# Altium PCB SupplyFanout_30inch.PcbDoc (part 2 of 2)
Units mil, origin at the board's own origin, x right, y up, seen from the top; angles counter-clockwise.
Board outline 6605 x 4500 mil, 4 copper layers (Top Layer, Int1 (GND), Int2 (PWR), Bottom Layer), stack 53.912 mil thick; 152 components, 62 nets, 512 pads, 47 vias.
Unrouted connection lines stored in the file: 85.
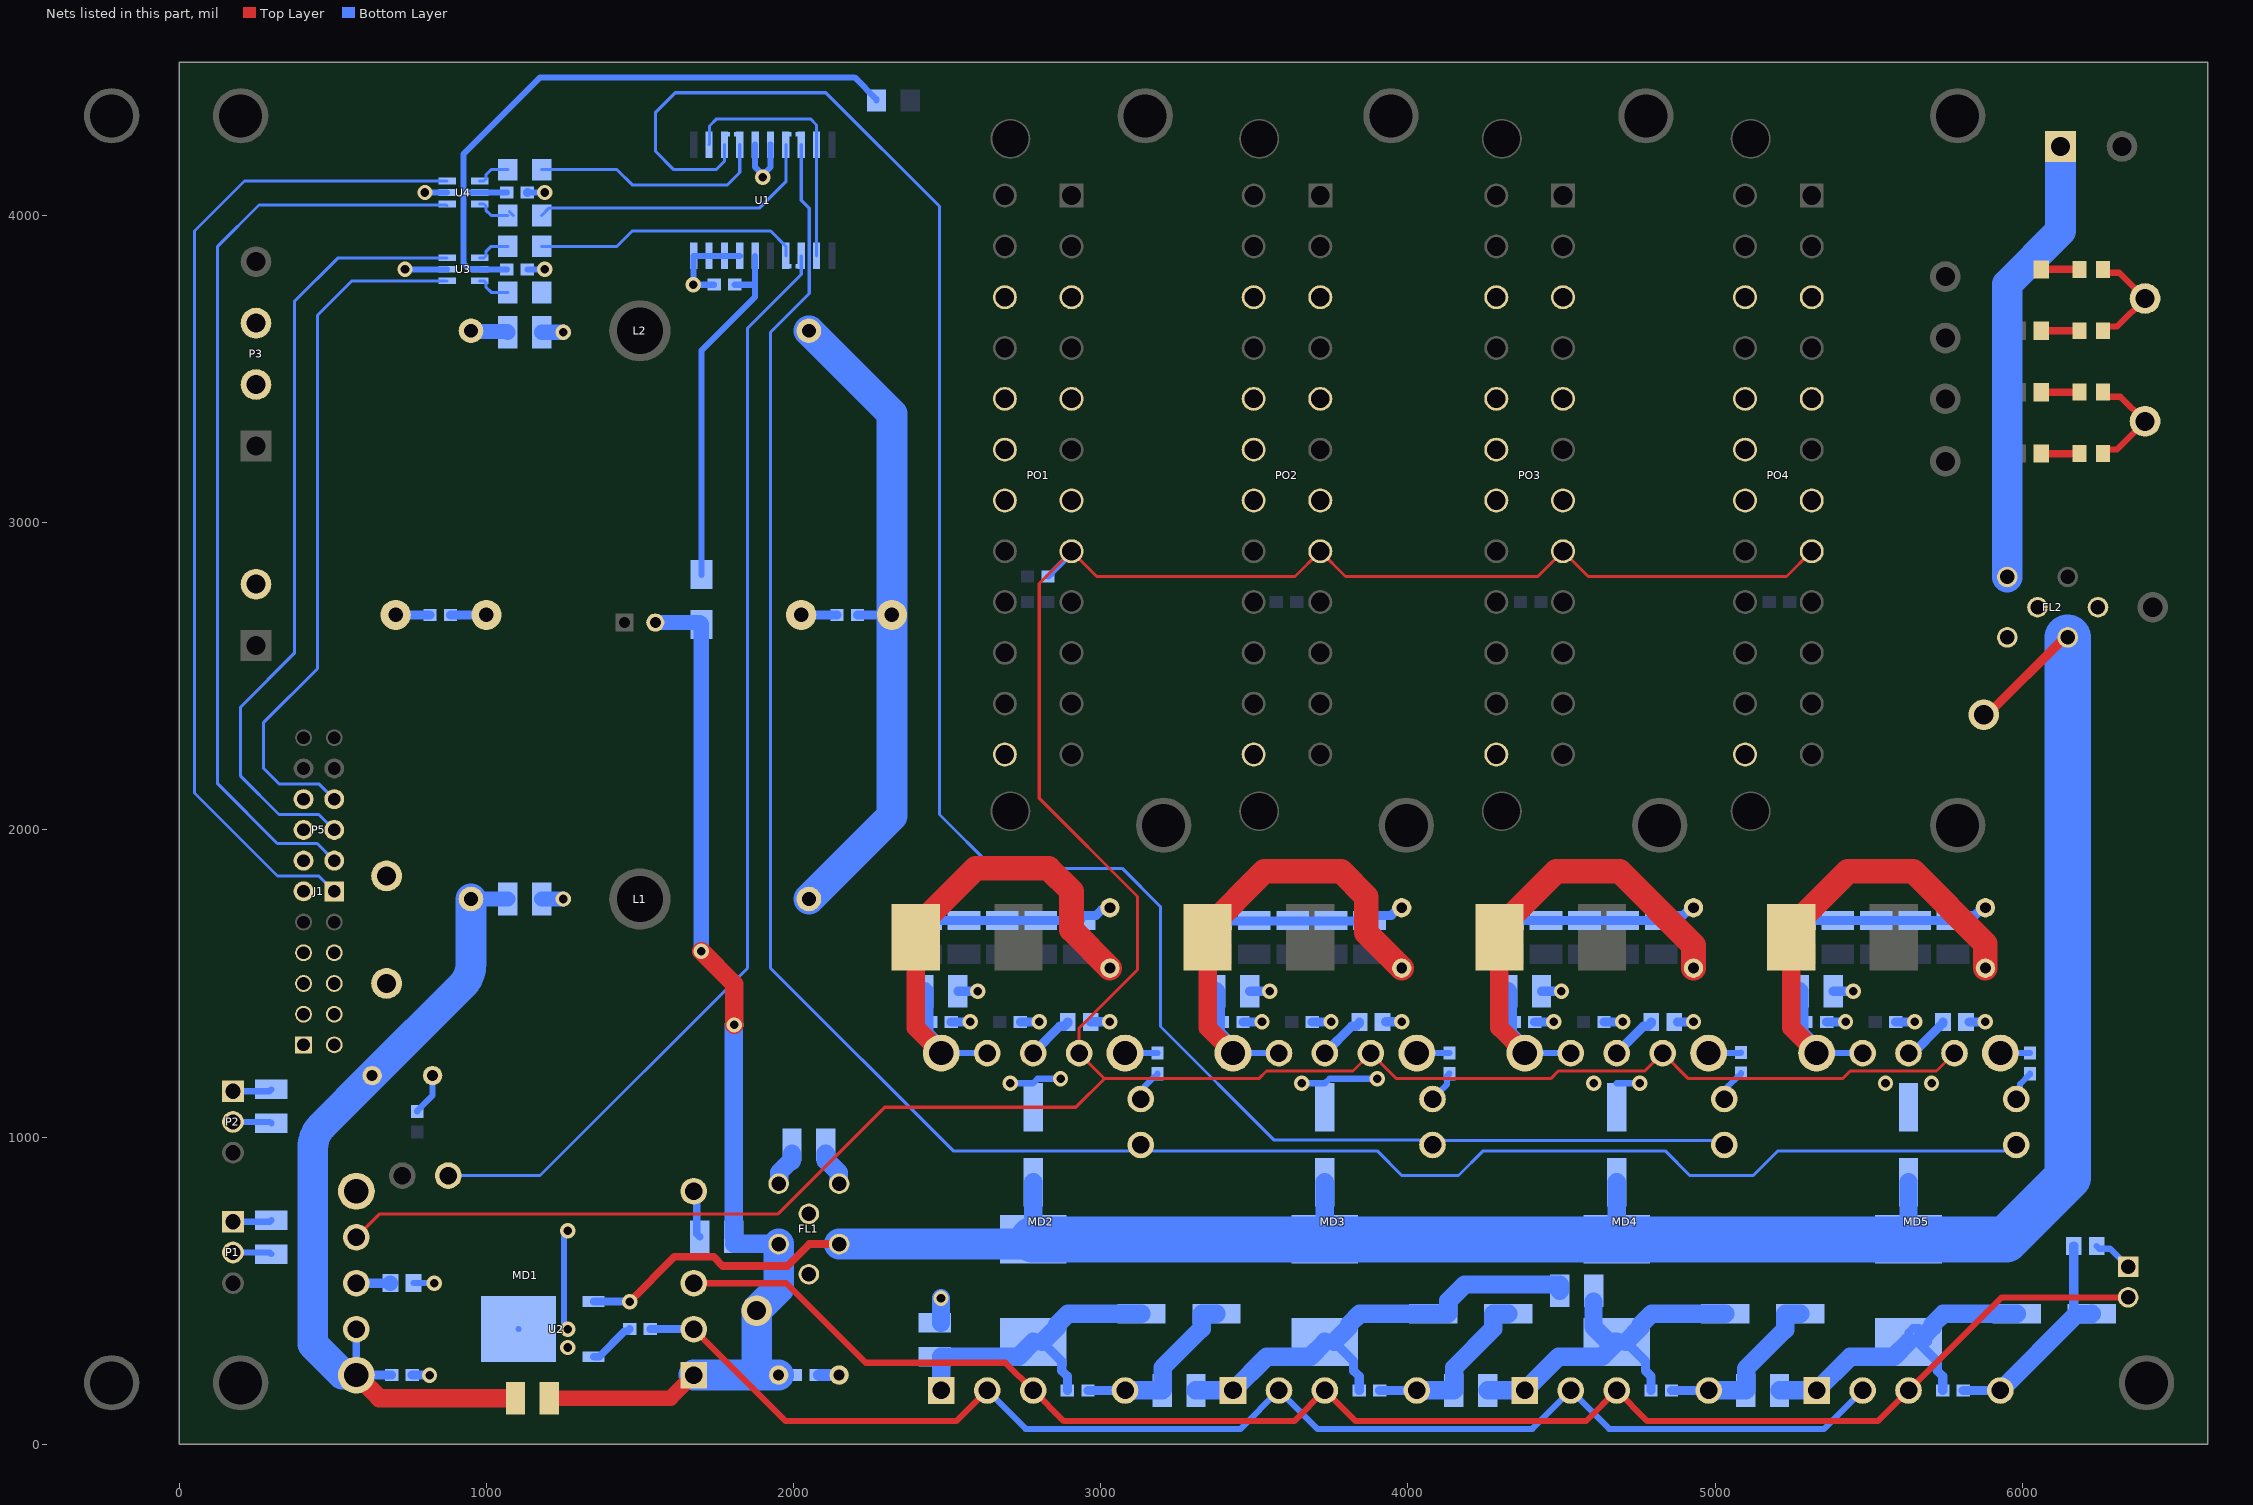
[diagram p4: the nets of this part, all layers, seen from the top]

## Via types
v1: diameter 50, hole 28, Top Layer to Bottom Layer, tented both sides, 43 vias
v2: diameter 100, hole 58, Top Layer to Bottom Layer, tented both sides, 4 vias

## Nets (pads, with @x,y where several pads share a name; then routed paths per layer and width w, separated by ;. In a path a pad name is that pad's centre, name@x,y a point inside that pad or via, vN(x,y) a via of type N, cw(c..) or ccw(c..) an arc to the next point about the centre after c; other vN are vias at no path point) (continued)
FGND: C1.2 C2.2 C3.2 C4.2 C57.1 C58.1 C59.1 C61.1 C62.1 C65.1 C66.1 C67.1 C68.1 FGND.1 FL1.4 FL1.5 FL1.6 J1.01 J1.02 J1.03 J1.04 MD1.3 MD1.4 P1.1 P2.1 R22.1 R28.2 R29.2 | length 1231.8
  Bottom Layer w20: P1.1@175,724.21 295.26,724.21 C67.1@300,728.95 ; P2.1@175,1149.21 294.09,1149.21 C68.1@300,1155.12 ; MD1.4@576.57,823.43 MD1.4@580,826.85 ; R29.2@762.4,525 762.5,524.9 829.31,524.9 v1(830,524.21) ; R28.2@775,1083.46 775,1085.43 825,1135.43 C2.2@825,1200
  Bottom Layer w25: MD1.3@1675,823.43 1685,813.43 1685,684.88 C59.1@1694.88,675
  Bottom Layer w30: C66.1@758.46,225 v1(815,225) ; C65.1@883.46,2700 C1.2@1000,2700 ; C4.2@2025,2700 C57.1@2141.54,2700
  Bottom Layer w40: C58.1@2083.46,225 C3.2@2148.43,225
  Bottom Layer w50: C61.1@1180.12,1775 v1(1250,1775) ; C62.1@1180.12,3620 v1(1250,3620)
  Bottom Layer w60: FL1.4@1951.57,848.43 1952.9,849.75 1952.9,884.56 1990.19,921.85 1993.39,921.85 1994.88,923.35 R22.1@1994.88,945
FPWR: C1.1 C62.2 C65.2 C67.2 C68.2 FPWR.1 J1.05 J1.06 J1.07 J1.08 L2.1 P1.2 P2.2 | length 487.8
  Bottom Layer w20: P1.2@175,624.21 294.5,624.21 C67.2@300,618.71 ; P2.2@175,1049.21 295.67,1049.21 C68.2@300,1044.88
  Bottom Layer w30: C1.1@704.72,2700 C65.2@816.54,2700
  Bottom Layer w50: L2.1@950,3625 952.5,3622.5 1067.38,3622.5 C62.2@1069.88,3620
GND: C5.2 C6.2 C7.2 C8.2 C9.2 C10.1 C11.1 C12.2 C13.1 C14.1 C15.1 C16.1 C17.1 C18.1 C19.2 C20.1 C21.1 C22.1 C23.1 C24.2 C25.1 C26.1 C27.1 C28.1 C29.1 C30.1 C31.2 C32.1 C33.1 C34.1 C35.1 C36.2 C37.1 C38.1 C39.1 C40.1 C41.1 C42.1 C43.2 C44.1 C45.1 C46.1 C47.1 C48.2 C49.1 C50.1 C51.1 C52.1 C53.1 C54.1 C55.1 C56.1 C60.1 C63.1 C64.1 DS1.1 DS2.1 DS3.1 DS4.1 FL1.3 FL2.4 FL2.5 FL2.6 GND.1 J1.11 J1.13 J1.15 J1.17 MD2.3 MD2.4 MD3.3 MD3.4 MD4.3 MD4.4 MD5.3 MD5.4 P3.2 P3.3 P4.2 P5.2 P5.4 P5.6 P5.8 PO1.3 PO1.5 PO1.7 PO1.15 PO1.17 PO1.18 PO1.19 PO1.24 PO2.3 PO2.5 PO2.7 PO2.15 PO2.17 PO2.18 PO2.19 PO2.24 PO3.3 PO3.5 PO3.7 PO3.15 PO3.17 PO3.18 PO3.19 PO3.24 PO4.3 PO4.5 PO4.7 PO4.15 PO4.17 PO4.18 PO4.19 PO4.24 R6.1 R7.2 R8.2 R10.2 R11.2 R14.2 R15.2 R17.2 R18.2 R22.2 U1.5 U1.6 U1.17 U1.18 U1.19 U1.20 U2.4 U3.2 U4.2 | length 9004.6
  Top Layer w20: DS1.1@6263.39,3225 6263.39,3225.36 6276.02,3238 6308,3238 GND.1@6400,3330 6320.03,3409.97 6276.02,3409.97 6263.39,3422.61 DS2.1@6263.39,3425 ; DS3.1@6263.39,3625 6263.39,3626.63 6276.02,3639.27 6309.27,3639.27 GND.1@6400,3730 6316.02,3813.98 6274.41,3813.98 DS4.1@6263.39,3825
  Bottom Layer w20: v1(735,3825) U3.2@871.85,3825 ; v1(800,4075) U4.2@871.85,4075 ; C63.1@1133.46,3825 v1(1190,3825) ; C64.1@1133.76,4075 1133.91,4075.15 1189.85,4075.15 v1(1190,4075) ; v1@1252.5,375 1252.5,674.38 1265,686.88 v1(1265,695) ; C60.1@1741.54,3775 v1(1673.9,3775) 1674.45,3775.55 1674.45,3868.35 U1.20@1675,3868.9 U1.19@1725,3868.9 U1.18@1775,3868.9 U1.17@1825,3868.9 ; U1.5@1875,4231.1 1875,4157.8 v1@1900,4132.8 ; v1(1900,4125) v1@1900,4132.8 ; U1.6@1925,4231.1 1925,4157.8 v1@1900,4132.8 ; C55.1@2480,395.12 C55.1@2489.88,405 ; v1(2705,1175) 2780,1175 2794.61,1189.61 v1(2869.33,1189.61) ; MD2.4@3079.21,1273.43 3184.96,1273.43 R17.2@3185,1273.46 ; v1(3655,1175) 3730,1175 3745,1190 v1(3900,1190) ; MD3.4@4029.21,1273.43 4134.96,1273.43 R14.2@4135,1273.46 ; C24.2@4680,1175 v1(4755,1175) ; MD4.4@4979.21,1273.43 5083.43,1273.43 R10.2@5085,1275 ; MD5.4@5929.21,1273.43 R7.2@6024.98,1273.44
  Bottom Layer w30: C64.1@1133.46,4075.29 C64.1@1133.76,4075 ; C56.1@2430,1705.12 C52.1@2555,1705.12 C51.1@2680,1705.12 C49.1@2805,1705.12 C47.1@2930,1705.12 2946.5,1721.61 2985,1721.61 3003.69,1740.3 3023.64,1740.3 C5.2@3029.96,1746.61 ; C54.1@2513.46,1375 v1(2575,1375) ; C53.1@2535.12,1475 v1(2600,1475) ; C50.1@2738.46,1375 v1(2800,1375) ; C46.1@2958.46,175 MD2.3@3079.21,175 ; R18.2@2967.4,1375 R18.2@2967.4,1375 3029.96,1375.04 v1(3030,1375.09) ; C44.1@3375,1703.31 3875,1703.31 3893.31,1721.61 3946.07,1721.61 3971.07,1746.61 C6.2@3980,1746.61 ; C42.1@3463.46,1375 v1(3525,1375) ; C41.1@3485.12,1475 v1(3550,1475) ; C38.1@3688.46,1375 v1(3750,1375) ; C34.1@3908.46,175 MD3.3@4029.21,175 ; R15.2@3927.72,1375.09 v1(3980,1375.09) ; C32.1@4325,1705.12 C27.1@4575,1705.12 C23.1@4824.62,1705.12 4825,1705.12 4841.5,1721.61 4896.07,1721.61 4921.07,1746.61 C7.2@4930,1746.61 ; C30.1@4413.46,1375 v1(4475,1375) ; C29.1@4435.12,1475 v1(4500,1475) ; C26.1@4638.46,1375 v1(4700,1375) ; C22.1@4858.46,175 MD4.3@4979.21,175 ; R11.2@4877.72,1375 v1(4930,1375) ; C20.1@5275,1705.12 C16.1@5400,1705.12 C15.1@5525,1705.12 C13.1@5650,1705.12 C11.1@5775,1705.12 5791.5,1721.61 5846.35,1721.61 5871.35,1746.61 C8.2@5880.28,1746.61 ; C18.1@5363.46,1375 v1(5425,1375) ; C17.1@5385.12,1475 v1(5450,1475) ; C14.1@5588.46,1375 v1(5650,1375) ; C10.1@5808.46,175 MD5.3@5929.21,175 ; R8.2@5827.99,1375 v1(5880.28,1375) ; R6.1@6167.6,645 6167.6,441.5 6184.09,425 C9.2@6186.61,425
  Bottom Layer w60: R22.2@2105.12,945 2105.12,923.35 2106.61,921.85 2109.81,921.85 2147.1,884.56 2147.1,849.75 FL1.3@2148.43,848.43 ; C55.1@2480,395.12 v1(2480,475) ; MD2.3@3079.21,175 C45.1@3199.88,175 3201.38,176.5 3201.38,249.33 3328.31,376.26 3328.31,423.5 3329.8,425 C43.2@3377.05,425 ; MD3.3@4029.21,175 C33.1@4149.88,175 4151.38,176.5 4151.38,249.33 4278.31,376.26 4278.31,423.5 4279.8,425 C31.2@4327.05,425 ; MD4.3@4979.21,175 C21.1@5099.88,175 5101.38,176.5 5101.38,246.38 5228.31,373.31 5228.31,423.5 5229.8,425 C19.2@5277.05,425 ; MD5.3@5929.21,175 6177.72,423.5 6225.55,423.5 C9.2@6227.05,425
  other v1: 1264.45,315 1264.45,374.61 4605,1175 5555,1175 5705,1175
Net+24V_1: +24V.1 C12.1 C24.1 C36.1 C48.1 FL1.1 FL2.2 L7.1 L8.1 L9.1 L10.1 U2.1 | length 7871.1
  Top Layer w25: v1(1466.42,464.39) 1612.03,610 1740,610 1770,580 1979.21,580 2050.79,651.57 FL1.1@2148.43,651.57
  Top Layer w30: +24V.1@5875,2375 5886.86,2375 6138.43,2626.57 FL2.2@6148.43,2626.57
  Bottom Layer w25: U2.1@1349.09,464.37 v1(1466.42,464.39)
  Bottom Layer w60: L10.1@2780,667 C48.1@2780,852.95 ; L9.1@3730,667 C36.1@3730,852.95 ; L8.1@4680,667 C24.1@4680,852.95 ; L7.1@5630,667 C12.1@5630,852.95
  Bottom Layer w100: FL1.1@2148.43,651.57 2764.57,651.57 L10.1@2780,667
  Bottom Layer w150: L10.1@2780,667 L9.1@3730,667 L8.1@4680,667 L7.1@5630,667 5947,667 6148.43,868.43 FL2.2@6148.43,2626.57
NetC2_1: C2.1 C61.2 C66.2 L1.2 MD1.7 MD1.8 R1.1 | length 2771.5
  Top Layer w60: MD1.8@576.57,225 651.57,150 R1.1@1094.88,150
  Bottom Layer w25: MD1.8@576.57,225 MD1.7@576.57,374.61
  Bottom Layer w30: MD1.8@576.57,225 C66.2@691.54,225
  Bottom Layer w50: L1.2@950,1775 C61.2@1069.88,1775
  Bottom Layer w100: MD1.8@576.57,225 572.73,228.84 531.16,228.84 435,325 435,965.57 cw(c535,965.43) 464.17,1036.02 628.15,1200 920.83,1492.68 ccw(c850,1563.27) 950,1563.27 L1.2@950,1775
NetC3_1: C3.1 C58.2 C59.2 D1.1 FL1.2 MD1.1 P6.2 R1.2 TP1.1 | length 3571.1
  Top Layer w50: R1.2@1205.12,150 1600,150 MD1.1@1675,225
  Top Layer w60: v1(1700,1605) 1806.61,1498.39 v1(1806.61,1365)
  Bottom Layer w50: P6.2@1550,2675 1695,2675 1700,2670 v1(1700,1605)
  Bottom Layer w60: C59.2@1805.12,675 1805.12,1363.5 v1(1806.61,1365) ; C59.2@1806.61,652.9 1950.25,652.9 FL1.2@1951.57,651.57
  Bottom Layer w100: MD1.1@1675,225 1880,225 ; C3.1@1951.57,225 1880,225 ; FL1.2@1951.57,651.57 1951.57,506.57 TP1.1@1880,435 1880,225
NetC4_1: C4.1 C57.2 L1.1 L2.2 | length 2185.7
  Bottom Layer w30: C57.2@2208.46,2700 C4.1@2320.28,2700
  Bottom Layer w100: L1.1@2050,1775 2320.28,2045.28 C4.1@2320.28,2700 2320.28,3354.72 L2.2@2050,3625
NetC5_1: C5.1 C53.2 C54.2 L3.1 MD2.7 MD2.8 | length 1736
  Top Layer w60: L3.1@2398,1650 2398,1356.21 MD2.8@2480.79,1273.43
  Top Layer w80: L3.1@2398,1650 2398,1680 2593,1875 2830,1875 2905,1800 2905,1674.72 C5.1@3029.96,1549.76
  Bottom Layer w20: MD2.8@2480.79,1273.43 MD2.7@2630.39,1273.43
  Bottom Layer w60: C53.2@2424.88,1475 2424.88,1336.33 2480.79,1280.42 MD2.8@2480.79,1273.43
NetC6_1: C6.1 C41.2 C42.2 L4.1 MD3.7 MD3.8 | length 1723.6
  Top Layer w60: L4.1@3348,1650 3348,1356.21 MD3.8@3430.79,1273.43
  Top Layer w80: L4.1@3348,1650 3348,1680 3533,1865 3782.89,1865 3865,1782.89 3865,1664.76 C6.1@3980,1549.76
  Bottom Layer w20: MD3.8@3430.79,1273.43 MD3.7@3580.39,1273.43
  Bottom Layer w60: C41.2@3374.88,1475 3374.88,1336.33 3430.79,1280.42 MD3.8@3430.79,1273.43
NetC7_1: C7.1 C29.2 C30.2 L5.1 MD4.7 MD4.8 | length 1698.5
  Top Layer w60: L5.1@4298,1650 4298,1356.21 MD4.8@4380.79,1273.43
  Top Layer w80: L5.1@4298,1650 4298,1680 4483,1865 4690,1865 4930,1625 C7.1@4930,1549.76
  Bottom Layer w20: MD4.8@4380.79,1273.43 MD4.7@4530.39,1273.43
  Bottom Layer w60: C29.2@4324.88,1475 4324.88,1336.33 4380.79,1280.42 MD4.8@4380.79,1273.43
NetC8_1: C8.1 C17.2 C18.2 L6.1 MD5.7 MD5.8 | length 1701.5
  Top Layer w60: L6.1@5248,1650 5248,1356.21 MD5.8@5330.79,1273.43
  Top Layer w80: L6.1@5248,1650 5248,1680 5286.5,1718.5 5433,1865 5645,1865 5880.28,1629.72 C8.1@5880.28,1549.76
  Bottom Layer w20: MD5.8@5330.79,1273.43 MD5.7@5480.39,1273.43
  Bottom Layer w60: C17.2@5274.88,1475 5274.88,1336.33 5330.79,1280.42 MD5.8@5330.79,1273.43
NetC9_1: C9.1 C10.2 C21.2 L7.2 MD5.1 | length 1238.5
  Bottom Layer w25: L7.2@5630,333 5693.34,333 5677.54,365.94 5665.36,378.12 5644.64,378.12 5630,363.47 5630,355.12 L7.2@5630,333
  Bottom Layer w30: L7.2@5630,333 5660,333 5723.5,269.5 5723.5,239.5 5741.54,221.46 C10.2@5741.54,175
  Bottom Layer w60: C21.2@5210.12,175 MD5.1@5330.79,175 5440.79,285 5582,285 L7.2@5630,333 ; L7.2@5676.67,349.67 5708.5,381.5 5708.5,389.85 5743.65,425 C9.1@5982.95,425
NetC19_1: C19.1 C22.2 C33.2 L8.2 MD4.1 R12.2 | length 1251.3
  Bottom Layer w30: L8.2@4680,333 4710,333 4773.5,269.5 4773.5,239.5 4791.54,221.46 C22.2@4791.54,175
  Bottom Layer w60: C33.2@4260.12,175 MD4.1@4380.79,175 4490.79,285 4632,285 L8.2@4680,333 4652.92,333 4604.42,381.5 R12.2@4604.42,464.04 ; L8.2@4710,333 4758.5,381.5 4758.5,389.85 4793.65,425 C19.1@5032.95,425
NetC31_1: C31.1 C34.2 C45.2 L9.2 MD3.1 R12.1 | length 1567
  Bottom Layer w30: L9.2@3730,333 3760,333 3823.5,269.5 3823.5,239.5 3841.54,221.46 C34.2@3841.54,175
  Bottom Layer w60: C45.2@3310.12,175 MD3.1@3430.79,175 3540.79,285 3682,285 L9.2@3730,333 ; L9.2@3760,333 3808.5,381.5 3808.5,389.85 3843.65,425 4130.2,425 4131.69,426.5 4131.69,466.69 4185,520 4493.39,520 4494.88,518.5 R12.1@4494.88,500
NetC43_1: C43.1 C46.2 C55.2 L10.2 MD2.1 | length 1017.9
  Bottom Layer w30: L10.2@2780,333 2810,333 2873.5,269.5 2873.5,239.5 2891.54,221.46 C46.2@2891.54,175
  Bottom Layer w60: MD2.1@2480.79,175 2480.39,175.39 2480.39,284.49 2480,284.88 2480.12,285 2732,285 L10.2@2780,333 ; L10.2@2810,333 2858.5,381.5 2858.5,389.85 2893.65,425 C43.1@3132.95,425
NetC60_2: C60.2 D1.2 U1.16 | length 1177.2
  Bottom Layer w20: D1.2@1700,2830.71 1700,3560 1875,3735 1875,3775 ; C60.2@1808.46,3775 1875,3775 ; U1.16@1875,3868.9 1875,3775
NetDS1_2: DS1.2 R2.2 | length 124.2
  Top Layer w25: R2.2@6062.4,3225 DS1.2@6186.61,3225
NetDS2_2: DS2.2 R3.2 | length 124.2
  Top Layer w25: R3.2@6062.4,3425 DS2.2@6186.61,3425
NetDS3_2: DS3.2 R4.2 | length 124.2
  Top Layer w25: R4.2@6062.4,3625 DS3.2@6186.61,3625
NetDS4_2: DS4.2 R5.2 | length 124.2
  Top Layer w25: R5.2@6062.4,3825 DS4.2@6186.61,3825
NetFL2_3: FL2.3 P7.1 | length 1473.4
  Bottom Layer w100: FL2.3@5951.57,2823.43 5951.57,3776.57 6125,3950 P7.1@6125,4225
NetMD1_6: MD1.6 R29.1 | length 112.4
  Bottom Layer w30: MD1.6@576.57,524.21 686.81,524.21 R29.1@687.6,525
  Bottom Layer w50: R29.1@687.01,524.21 687.6,524.8 R29.1@687.6,525
NetMD1_32: MD1.32 R32.2 U1.13 | length 3645.3
  Bottom Layer w10: MD1.32@875.79,874.62 1174.62,874.62 1850,1550 1850,3633.46 2025,3808.46 U1.13@2025,3868.9
NetMD2_6: MD2.6 R18.1 | length 157
  Bottom Layer w30: MD2.6@2780,1273.43 2867.05,1360.47 2882.01,1360.47 2892.6,1371.06 R18.1@2892.6,1375
NetMD2_32: MD2.32 MD5.32 R31.2 U1.8 | length 7202.5
  Bottom Layer w10: U1.8@2025,4231.1 2025,4050 2051.19,4023.81 2051.19,3746.19 1925,3620 1925,1550 2520,955 3090.46,955 3109.67,974.21 MD2.32@3130.4,974.21 3151.14,974.21 3170.35,955 3900,955 3980,875 4165,875 4245,955 4837.72,955 4917.72,875 5125,875 5205,955 5940.46,955 5959.67,974.21 MD5.32@5980.4,974.21
NetMD2_33: MD2.33 R17.1 | length 106.5
  Bottom Layer w20: MD2.33@3130.4,1123.82 3143.15,1136.56 3143.15,1164.69 3173.35,1194.88 3175.31,1194.88 3185,1204.57 R17.1@3185,1206.54
NetMD3_6: MD3.6 R15.1 | length 157
  Bottom Layer w30: MD3.6@3730,1273.43 3817.05,1360.47 3832.01,1360.47 3842.6,1371.06 R15.1@3842.6,1375
NetMD3_32: MD3.32 MD4.32 R30.2 U1.3 | length 6767.2
  Bottom Layer w10: U1.3@1775,4231.1 1775,4177.24 1747.29,4149.53 1610.47,4149.53 1550,4210 1550,4335 1615,4400 2105,4400 2475,4030 2475,2050 2650,1875 3070,1875 3195,1750 3195,1360 3565,990 4036.24,990 4037.37,988.87 4065.75,988.87 MD3.32@4080.4,974.21 4095.06,988.87 5015.75,988.87 MD4.32@5030.4,974.21
NetMD3_33: MD3.33 R14.1 | length 105.3
  Bottom Layer w20: MD3.33@4080.4,1123.82 4127.18,1170.59 4127.18,1198.72 R14.1@4135,1206.54
NetMD4_6: MD4.6 R11.1 | length 157
  Bottom Layer w30: MD4.6@4680,1273.43 4767.05,1360.47 4782.01,1360.47 4792.6,1371.06 R11.1@4792.6,1375
NetMD4_33: MD4.33 R10.1 | length 108
  Bottom Layer w20: MD4.33@5030.4,1123.82 5043.15,1136.56 5043.15,1166.22 5073.35,1196.42 5075.31,1196.42 5085,1206.1 R10.1@5085,1208.07
NetMD5_6: MD5.6 R8.1 | length 157
  Bottom Layer w30: MD5.6@5630,1273.43 5644.96,1273.43 5732.01,1360.47 5742.6,1371.06 R8.1@5742.6,1375
NetMD5_33: MD5.33 R7.1 | length 101.2
  Bottom Layer w20: MD5.33@5980.4,1123.82 5993.15,1136.56 5993.15,1172.72 6025,1204.57 R7.1@6025,1206.54
NetP8_1: P8.1 R6.2 | length 130.3
  Bottom Layer w20: R6.2@6242.4,645 6250.84,636.56 6286.28,636.56 P8.1@6344.88,577.95
NetR23_2: R23.2 U2.3 | length 154.8
  Bottom Layer w25: U2.3@1349.09,284.84 1366.81,284.84 1449.78,367.81 1459.35,367.81 R23.2@1466.54,375
NetR24_2: R24.2 U3.6 | length 115.6
  Bottom Layer w10: U3.6@978.15,3787.6 992.29,3787.6 998.12,3781.77 998.12,3767.63 1015.75,3750 R24.2@1069.88,3750
NetR25_2: R25.2 U3.4 | length 115.6
  Bottom Layer w10: U3.4@978.15,3862.4 992.29,3862.4 998.12,3868.23 998.12,3882.37 1015.75,3900 R25.2@1069.88,3900
NetR26_2: R26.2 U4.6 | length 133.4
  Bottom Layer w10: U4.6@978.15,4037.6 992.29,4037.6 998.12,4031.77 998.12,4017.63 1015.75,4000 R26.2@1069.88,4000 ; R26.2@1075,4012.6 R26.2@1087.6,4000
NetR27_2: R27.2 U4.4 | length 115.4
  Bottom Layer w10: U4.4@978.15,4112.4 992.29,4112.4 998.12,4118.23 998.12,4132.37 1015.28,4149.53 R27.2@1069.88,4149.53
ON/OFF: MD1.2 MD2.2 MD3.2 MD4.2 MD5.2 P8.2 | length 5188.5
  Top Layer w20: MD1.2@1675,524.21 1975.79,524.21 2235,265 2690,265 MD2.2@2780,175 2880,75 3630,75 MD3.2@3730,175 3830,75 4580,75 MD4.2@4680,175 4780,75 5530,75 MD5.2@5630,175 5932.95,477.95 P8.2@6344.88,477.95
PG: MD1.5 MD2.5 MD3.5 MD4.5 MD5.5 PO1.8 PO2.8 PO3.8 PO4.8 R19.2 | length 10326.3
  Top Layer w10: MD1.5@576.58,673.83 652.75,750 1950,750 2297.05,1097.05 2919.21,1097.05 3012.16,1190 ; PO4.8@5315,2906.12 PO4.8@5315,2907.2 5232.8,2825 4587.2,2825 PO3.8@4505,2907.2 4422.8,2825 3797.2,2825 PO2.8@3715,2907.2 3632.8,2825 2987.2,2825 PO1.8@2905,2907.2 2800,2802.2 2800,2102.89 3120,1782.89 3120,1545 2929.62,1354.62 MD2.5@2929.62,1273.42 2929.62,1272.55 3012.17,1190 ; MD5.5@5779.62,1273.42 5721.31,1215.12 5440.12,1215.12 5415,1190 4913.04,1190 MD4.5@4829.62,1273.42 4771.2,1215 4490,1215 4465,1190 3963.04,1190 MD3.5@3879.62,1273.42 3821.2,1215 3540,1215 3515,1190 3012.17,1190
  Bottom Layer w20: R19.2@2828.46,2825 2830.43,2825 2840.12,2834.69 2840.12,2836.65 2905,2901.54 PO1.8@2905,2907.2
SEQ3V3: MD1.34 MD2.34 MD3.34 MD4.34 MD5.34 R23.1 | length 4423.3
  Top Layer w20: MD1.34@1675,374.62 1974.62,75 2530.41,75 MD2.34@2630.4,175
  Bottom Layer w20: MD2.34@2630.4,175 2755.4,50 3455.41,50 MD3.34@3580.4,175 3705.4,50 4405.41,50 MD4.34@4530.4,175 4655.4,50 5355.41,50 MD5.34@5480.4,175
  Bottom Layer w25: R23.1@1533.46,375 1533.66,374.81 1674.81,374.81 MD1.34@1675,374.62
SYNC00: R27.1 R30.1 U1.4 | length 773.1
  Bottom Layer w10: R27.1@1180.12,4149.53 1425.47,4149.53 1475,4100 1785,4100 1825,4140 U1.4@1825,4231.1
SYNC0: J1.12 P5.1 U4.3 | length 3306.4
  Bottom Layer w10: J1.12@504.72,1800 454.72,1850 320,1850 50,2120 50,3950 212.4,4112.4 U4.3@871.85,4112.4
SYNC1: J1.14 P5.3 U4.1 | length 3037.1
  Bottom Layer w10: J1.14@504.72,1900 449.2,1955.52 319.48,1955.52 125,2150 125,3900 259.68,4034.69 868.94,4034.69 U4.1@871.85,4031.77
SYNC2: J1.16 P5.5 U3.3 | length 2550.5
  Bottom Layer w10: J1.16@504.72,2000 454.72,2050 325,2050 200,2175 200,2400 375,2575 375,3720 517.4,3862.4 U3.3@871.85,3862.4
SYNC3: J1.18 P5.7 U3.1 | length 2287.1
  Bottom Layer w10: J1.18@504.72,2100 454.72,2150 325,2150 275,2200 275,2350 450,2525 450,3675 562.6,3787.6 U3.1@871.85,3787.6
SYNC45: R26.1 R31.1 U1.7 | length 961.5
  Bottom Layer w10: R26.1@1180.12,4000 1205.12,4025 1890,4025 1975,4110 U1.7@1975,4231.1
SYNC90: R25.1 R32.1 U1.14 | length 867.6
  Bottom Layer w10: R25.1@1180.12,3900 1425,3900 1475,3950 1925.39,3950 1975,3900.39 U1.14@1975,3868.9
SYNC135: R24.1
SYNCSELF: U1.2 U1.9 U1.12 | length 853.6
  Bottom Layer w10: U1.2@1725,4231.1 1726.44,4232.54 1726.44,4291.44 1750,4315 2055,4315 2075,4295 U1.9@2075,4231.1 U1.12@2075,3868.9
VCC: C63.2 C64.2 R21.2 U3.5 U4.5 | length 2128.5
  Bottom Layer w20: U4.5@978.15,4075 978.3,4075.15 1066.39,4075.15 C64.2@1066.54,4075.29 ; U4.5@978.15,4075.29 925.6,4075.29 925,4075.89 ; C63.2@1066.54,3825 U3.5@978.15,3825 977.32,3825.83 944.17,3825.83 925,3845 925,4075.89 ; R21.2@2269.88,4375 2269.88,4378.94 2198.82,4450 1175,4450 925,4200 925,4075.89
pads on no net: J1.09 J1.10 J1.19 J1.20 J1.21 J1.22 L1.11 L2.11 P1.3 P2.3 P5.9 P5.10 PO1.14 PO1.16 PO1.20 PO1.25 PO1.26 PO2.14 PO2.16 PO2.20 PO2.25 PO2.26 PO3.14 PO3.16 PO3.20 PO3.25 PO3.26 PO4.14 PO4.16 PO4.20 PO4.25 PO4.26 U1.15

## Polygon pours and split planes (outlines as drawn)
FGND on Int1 (GND) (split plane): 2299.9,3346.68 2299.9,2495 2299.9,2053.32 2085.79,1839.21 2083.29,1836.17 2081.43,1832.69 2080.29,1828.92 2079.9,1825 2079.9,1375 2079.9,638.43 2080.29,634.5 2081.43,630.73 2083.29,627.26 2085.79,624.21 2204.9,505.1 2204.9,203.32 2196.68,195.1 1433.32,195.1 1385.1,243.32 1385.1,455 1384.71,458.92 1383.57,462.69 1381.71,466.17 1379.21,469.21 1314.21,534.21 1311.17,536.71 1307.69,538.57 1303.92,539.71 1300,540.1 1230,540.1 1226.08,539.71 1222.31,538.57 1218.83,536.71 1215.79,534.21 1150.79,469.21 1148.29,466.17 1146.43,462.69 1145.29,458.92 1144.9,455 1144.9,243.32 1096.68,195.1 283.32,195.1 120.1,358.32 120.1,1631.68 168.32,1679.9 504.72,1679.9 508.65,1680.29 512.42,1681.43 515.89,1683.29 518.93,1685.79 589.21,1756.06 589.21,1756.07 591.71,1759.11 593.57,1762.59 594.71,1766.36 595.1,1770.28 595.1,3466.68 793.32,3664.9 1981.68,3664.9
GND on Int1 (GND) (split plane): 6584.9,20.1 20.1,20.1 20.1,4479.9 6584.9,4479.9
+3.3V1 on Int2 (PWR) (split plane): 5384.9,2261.68 5384.9,2211 5384.9,1875 5384.9,770.1 4295.1,770.1 4295.1,2276.68 4329.35,2310.93 5335.65,2310.93
+3.3V2 on Int2 (PWR) (split plane): 4029.9,2266.68 4029.9,1195.1 3537.54,1195.1 3263.42,1469.21 2835.1,1897.54 2835.1,2266.68 2879.35,2310.93 3985.65,2310.93
FPWR on Int2 (PWR) (split plane): 1029.9,3646.68 1029.9,3458.32 810.79,3239.21 808.29,3236.17 806.43,3232.69 805.29,3228.92 804.9,3225 804.9,1593.32 360.79,1149.21 358.29,1146.17 356.43,1142.69 355.29,1138.92 354.9,1135 354.9,428.32 316.68,390.1 163.32,390.1 120.1,433.32 120.1,1816.68 183.32,1879.9 504.72,1879.9 508.65,1880.29 512.42,1881.43 515.89,1883.29 518.93,1885.79 589.21,1956.07 591.71,1959.11 593.57,1962.58 594.71,1966.35 595.1,1970.28 595.1,3466.68 793.32,3664.9 1011.68,3664.9
+5V on Int2 (PWR) (split plane): 5384.9,3644.2 5384.9,3170.92 5190.79,2976.81 5188.29,2973.77 5186.43,2970.29 5185.29,2966.52 5184.9,2962.6 5184.9,2907.2 5184.9,2575 5184.9,2411 5184.9,2351.12 4321.03,2351.12 4317.11,2350.74 4313.34,2349.59 4309.86,2347.74 4306.82,2345.24 4260.79,2299.21 4258.29,2296.17 4256.43,2292.69 4255.29,2288.92 4254.9,2285 4254.9,785 4254.9,770.1 2788.32,770.1 2694.21,864.21 2395.1,1163.32 2395.1,1691.68 2589.21,1885.79 2591.71,1888.83 2593.57,1892.31 2594.71,1896.08 2595.1,1900 2595.1,3612.88 2702.21,3719.99 2704.71,3723.03 2706.57,3726.51 2707.71,3730.28 2708.1,3734.2 2708.1,4062 2707.71,4065.92 2706.57,4069.69 2704.71,4073.17 2702.21,4076.21 2389.21,4389.21 2386.17,4391.71 2382.69,4393.57 2378.92,4394.71 2375,4395.1 250,4395.1 246.08,4394.71 242.31,4393.57 238.83,4391.71 235.79,4389.21 135.79,4289.21 133.29,4286.17 131.43,4282.69 130.29,4278.92 129.9,4275 129.9,4115 129.9,4000 130.29,3996.08 131.43,3992.31 133.29,3988.83 135.79,3985.79 185.79,3935.79 188.83,3933.29 192.31,3931.43 196.08,3930.29 200,3929.9 281.68,3929.9 324.9,3886.68 324.9,3808.32 286.68,3770.1 20.1,3770.1 20.1,3825 20.1,4479.9 5384.9,4479.9
+12V on Int2 (PWR) (split plane): 6584.9,20.1 20.1,20.1 20.1,3729.9 295,3729.9 298.92,3730.29 302.69,3731.43 306.17,3733.29 309.21,3735.79 359.21,3785.79 361.71,3788.83 363.57,3792.31 364.71,3796.08 365.1,3800 365.1,3895 364.71,3898.92 363.57,3902.69 361.71,3906.17 359.21,3909.21 304.21,3964.21 301.17,3966.71 297.69,3968.57 293.92,3969.71 290,3970.1 208.32,3970.1 170.1,4008.32 170.1,4115 170.1,4266.68 258.32,4354.9 2366.68,4354.9 2667.9,4053.68 2667.9,3742.52 2560.79,3635.41 2558.29,3632.37 2556.43,3628.89 2555.29,3625.12 2554.9,3621.2 2554.9,1908.32 2360.79,1714.21 2358.29,1711.17 2356.43,1707.69 2355.29,1703.92 2354.9,1700 2354.9,1155 2355.29,1151.08 2356.43,1147.31 2358.29,1143.83 2360.79,1140.79 2665.79,835.79 2765.79,735.79 2768.83,733.29 2772.31,731.43 2776.08,730.29 2780,729.9 5405,729.9 5408.92,730.29 5412.69,731.43 5416.17,733.29 5419.21,735.79 5421.71,738.83 5423.57,742.31 5424.71,746.08 5425.1,750 5425.1,1875 5425.1,2211 5425.1,2270 5424.71,2273.92 5423.57,2277.69 5421.71,2281.17 5419.21,2284.21 5358.18,2345.24 5355.14,2347.74 5351.66,2349.59 5347.89,2350.74 5343.97,2351.12 5225.1,2351.12 5225.1,2411 5225.1,2575 5225.1,2907.2 5225.1,2954.28 5419.21,3148.39 5421.71,3151.43 5423.57,3154.91 5424.71,3158.68 5425.1,3162.6 5425.1,3644.2 5425.1,4479.9 6584.9,4479.9

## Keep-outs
Keep-Out Layer:
  lines w5: 0,0 6580,0 6605,0 6605,4500 0,4500 0,0

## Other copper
Bottom Layer:
  rectangle net GND: 1215,270 1290,480
  rectangle net GND: 2680,1150 2880,1200
  rectangle net GND: 3630,1150 3830,1200
  rectangle net GND: 4580,1150 4780,1200
  rectangle net GND: 5530,1150 5730,1200
Int1 (GND) (plane layer: these items are gaps in the copper):
  lines w40: 100,350 100,1640 160,1700 504.72,1700 575,1770.28 575,3475 785,3685 1990,3685 2320,3355 2320,2495 2320,2045 2100,1825 2100,1375 2100,638.43 2225,513.43 2225,195 2205,175 1425,175 1365,235 1365,455 1300,520 1230,520 1165,455 1165,235 1105,175 275,175 100,350
Int2 (PWR) (plane layer: these items are gaps in the copper):
  lines w40: 0,3825 0,3750 295,3750 345,3800 345,3895 290,3950 200,3950 150,4000 150,4115 ; 3249.21,1455 3529.21,1175 ; 4275,785 4275,750 ; 5205,2411 5205,2331.03 ; 150,4115 150,4275 250,4375 2375,4375 2688,4062 2688,3734.2 2575,3621.2 2575,1900 2375,1700 2375,1155 2680,850 2780,750 3540,750 4275,750 ; 150,4115 150,4115 ; 2815,1889.21 2815,1986.85 2815,2275 ; 2815,1889.21 3255,1449.21 3529.21,1175 ; 2815,1889.21 2815,2275 ; 2815,2275 2871.03,2331.03 3993.97,2331.03 4050,2275 4050,1175 3529.21,1175 ; 4275,750 4275,2285 4321.03,2331.03 5205,2331.03 ; 4275,750 5405,750 5405,1875 5405,2211 5405,2270 5343.97,2331.03 5205,2331.03 ; 5205,2331.03 5205,2575 5205,2907.2 5205,2962.6 5405,3162.6 5405,3644.2 5405,4500 ; 5405,4500 5405,4500 ; 100,425 100,1825 175,1900 504.72,1900 575,1970.28 575,3475 785,3685 890,3685 1020,3685 1050,3655 1050,3450 825,3225 825,1585 375,1135 375,420 325,370 155,370 100,425

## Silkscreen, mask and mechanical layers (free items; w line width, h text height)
Top Overlay:
  circle w60: c6405,200 r130
  circle w60: c5790,2015 r130
  circle w60: c4820,2015 r130
  circle w60: c3995,2015 r130
  circle w60: c3205,2015 r130
  circle w60: c5790,4325 r130
  circle w60: c4775,4325 r130
  circle w60: c3945,4325 r130
  circle w60: c3145,4325 r130
  circle w60: c200,4325 r130
  circle w60: c200,200 r130
  rectangle: 6125,700 6470,1750
  lines w5: 0,0 0,4500 6605,4500 6605,0 0,0
  lines w8: 50,474.21 50,374.21 275,374.21 275,474.21 ; 50,899.21 50,799.21 275,799.21 275,899.21
  text "+     -" at 6558.23,4104.98 h100 r180
  text "GPS" at 95.03,4005.01 h60
  text "24V IN" at 6060.05,3970.01 h60
  text "+  -  -  +" at 2.01,3868.9 h66 r270
  text "Fanout" at 95.05,2950.01 h60
  text "Self Sync" at 1250.08,2780.01 h60
  text "+  -" at 67.99,2579.04 h66 r90
  text "REV 2" at 6020.01,2469.93 h90 r270
  text "IO Power" at 6315,2470 h90 r270
  text "D2100068" at 6170.03,2469.48 h90 r270
  text "Header" at 165.01,2334.95 h60 r270
  text "Sync" at 255.01,2334.96 h60 r270
  text "S/N" at 6485.01,1344.96 h90 r270
  text "Fan Power +12V" at 745.13,10.01 h60
  text "+5V" at 2695.03,5.01 h60
  text "+3.3V2" at 3565.05,5.01 h60
  text "+3.3V1" at 4525.05,5.01 h60
  text "+12V" at 5525.03,5.01 h60
Bottom Overlay:
  circle w60: c1500,3625 r135
  circle w60: c1500,1775 r135
  circle w60: c200,4325 r130
  circle w60: c200,200 r130
  circle w60: c6405,200 r130
  circle w60: c5790,2015 r130
  circle w60: c4820,2015 r130
  circle w60: c3995,2015 r130
  circle w60: c3205,2015 r130
  circle w60: c5790,4325 r130
  circle w60: c4775,4325 r130
  circle w60: c3945,4325 r130
  circle w60: c3145,4325 r130
  text "Power Supply Part Number" at 1815,3395.01 h60
  text "I6A4W020A033V-005-R" at 1815,3295.01 h60
  text "Fan Inductor Part Number" at 1815,3215.01 h60
  text "1140-153K-RC" at 1815,3135.01 h60
  text "Filter Part Number" at 1815,3055.01 h60
  text "BNX016-01" at 1815,2975.01 h60
Mechanical 1:
  the board outline again, w5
